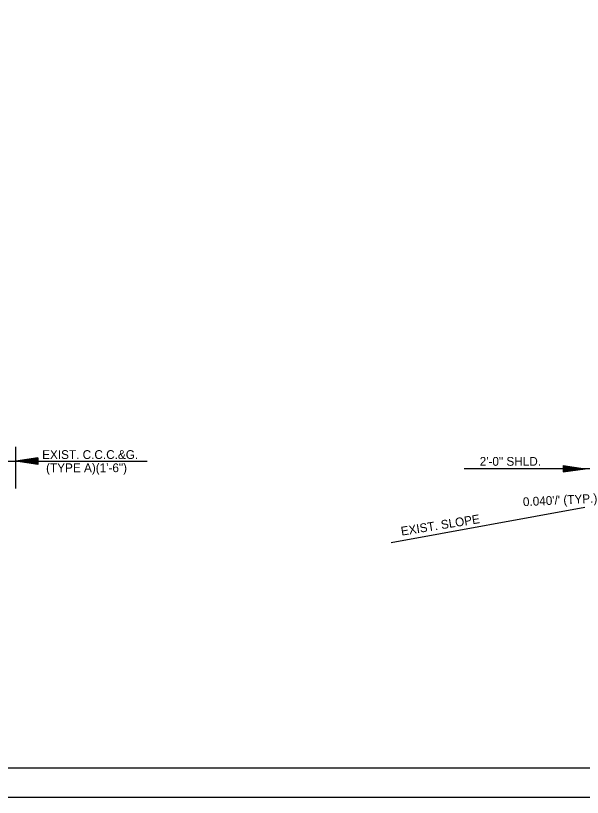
# Model space of a CAD drawing. Extents: x 2263886 to 2266026, y -3122850 to -3121850.
# Drawn here: x 2265920.8 to 2265959.5, y -3122443.8 to -3122390.5 of the extents above; entities that cross this region are included whole.
import ezdxf

# ---------------------------------------------------------------- set-up
doc = ezdxf.new("R2010")
doc.units = 0
for name, color, linetype in [('_CIVIL_CONSTRUCTION', 7, 'Continuous'), ('R_Border Prem', 7, 'Continuous'), ('R_Draft', 7, 'Continuous')]:
    doc.layers.add(name, color=color, linetype=linetype)

msp = doc.modelspace()

# ---------------------------------------------------------------- linework, layer by layer
at = {"layer": '_CIVIL_CONSTRUCTION'}
msp.add_line((2265859.035, -3122443.817), (2266025.702, -3122443.817), dxfattribs=at)
for points in [[(2265859.032, -3122337.151), (2266025.702, -3122337.151), (2266025.702, -3122443.82), (2265859.032, -3122443.82)], [(2265982.196, -3122339.098), (2265982.196, -3122344.038), (2266000.062, -3122344.038), (2266000.062, -3122345.498), (2266011.661, -3122345.498), (2266011.661, -3122357.664), (2266023.326, -3122357.664), (2266023.326, -3122441.828), (2265865.236, -3122441.828), (2265865.236, -3122339.098)]]:
    msp.add_lwpolyline(points, close=True, dxfattribs=at)
at = {"layer": 'R_Border Prem'}
for p, q in [((2265920.861, -3122422.753), (2265920.861, -3122419.897)), ((2265922.361, -3122420.662), (2265920.861, -3122420.887)), ((2265922.361, -3122420.699), (2265921.111, -3122420.887)), ((2265922.361, -3122420.737), (2265921.369, -3122420.887)), ((2265922.361, -3122420.775), (2265921.619, -3122420.887)), ((2265922.361, -3122420.814), (2265921.873, -3122420.887)), ((2265922.361, -3122420.662), (2265922.361, -3122421.112)), ((2265919.36, -3122420.886), (2265929.817, -3122420.886)), ((2265922.361, -3122421.112), (2265920.861, -3122420.887)), ((2265922.361, -3122421.074), (2265921.111, -3122420.887)), ((2265922.361, -3122421.036), (2265921.369, -3122420.887)), ((2265922.361, -3122420.998), (2265921.619, -3122420.887)), ((2265922.361, -3122420.96), (2265921.873, -3122420.887)), ((2265922.361, -3122420.851), (2265922.124, -3122420.887)), ((2265922.361, -3122420.922), (2265922.124, -3122420.887)), ((2265958.186, -3122421.169), (2265959.686, -3122421.394)), ((2265958.186, -3122421.169), (2265958.186, -3122421.619)), ((2265958.186, -3122421.206), (2265959.435, -3122421.394)), ((2265958.186, -3122421.244), (2265959.177, -3122421.394)), ((2265958.186, -3122421.282), (2265958.928, -3122421.394)), ((2265958.186, -3122421.321), (2265958.673, -3122421.394)), ((2265958.186, -3122421.358), (2265958.423, -3122421.394)), ((2265961.712, -3122421.394), (2265951.435, -3122421.394)), ((2265958.186, -3122421.619), (2265959.686, -3122421.394)), ((2265958.186, -3122421.467), (2265958.673, -3122421.394)), ((2265958.186, -3122421.543), (2265959.177, -3122421.394)), ((2265958.186, -3122421.581), (2265959.435, -3122421.394)), ((2265958.186, -3122421.505), (2265958.928, -3122421.394)), ((2265958.186, -3122421.429), (2265958.423, -3122421.394)), ((2265959.681, -3122424.032), (2265946.457, -3122426.46))]:
    msp.add_line(p, q, dxfattribs=at)
at = {"layer": 'R_Draft'}
msp.add_line((2266023.326, -3122441.828), (2265865.236, -3122441.828), dxfattribs=at)

# ---------------------------------------------------------------- texts
at = {"layer": 'R_Border Prem'}
for s, p in [('EXIST. C.C.C.&G.', (2265922.653, -3122420.733)), ('2\'-0" SHLD.', (2265952.5, -3122421.195)), ('(TYPE A)(1\'-6")', (2265922.923, -3122421.633))]:
    msp.add_text(s, height=0.6, dxfattribs=at).set_placement(p)
for s, rotation, p in [("0.040'/' (TYP.)", 2.8401, (2265955.462, -3122423.957)), ('EXIST. SLOPE', 9.1534, (2265947.174, -3122425.966))]:
    msp.add_text(s, height=0.6, rotation=rotation, dxfattribs=at).set_placement(p)

doc.saveas('drawing.dxf')
